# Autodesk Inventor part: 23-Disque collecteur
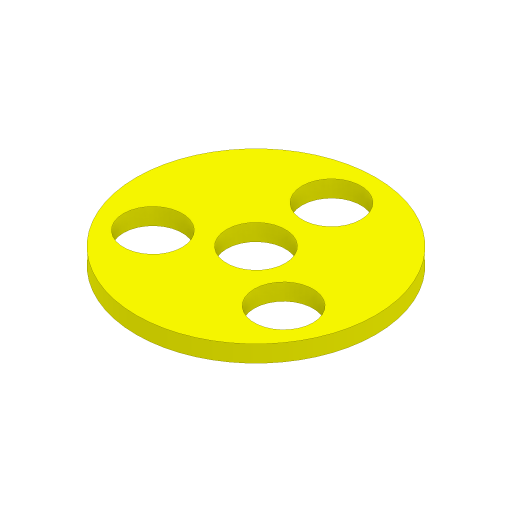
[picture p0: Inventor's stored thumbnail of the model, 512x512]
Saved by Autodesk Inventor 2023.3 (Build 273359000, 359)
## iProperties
Created: 2009-05
Part Number: 23-Disque collecteur
Material: Générique
Document SubType Name: Modeling
Designer: Papa
Density: 1 g/cm^3
Appearance: Par défaut
Sending System: SolidWorks 2008
Last Author: Roger
Last Saved: 2011-02-17
Author: Papa
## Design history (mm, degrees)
extrude "Extrusion1"
node "Solide1"
